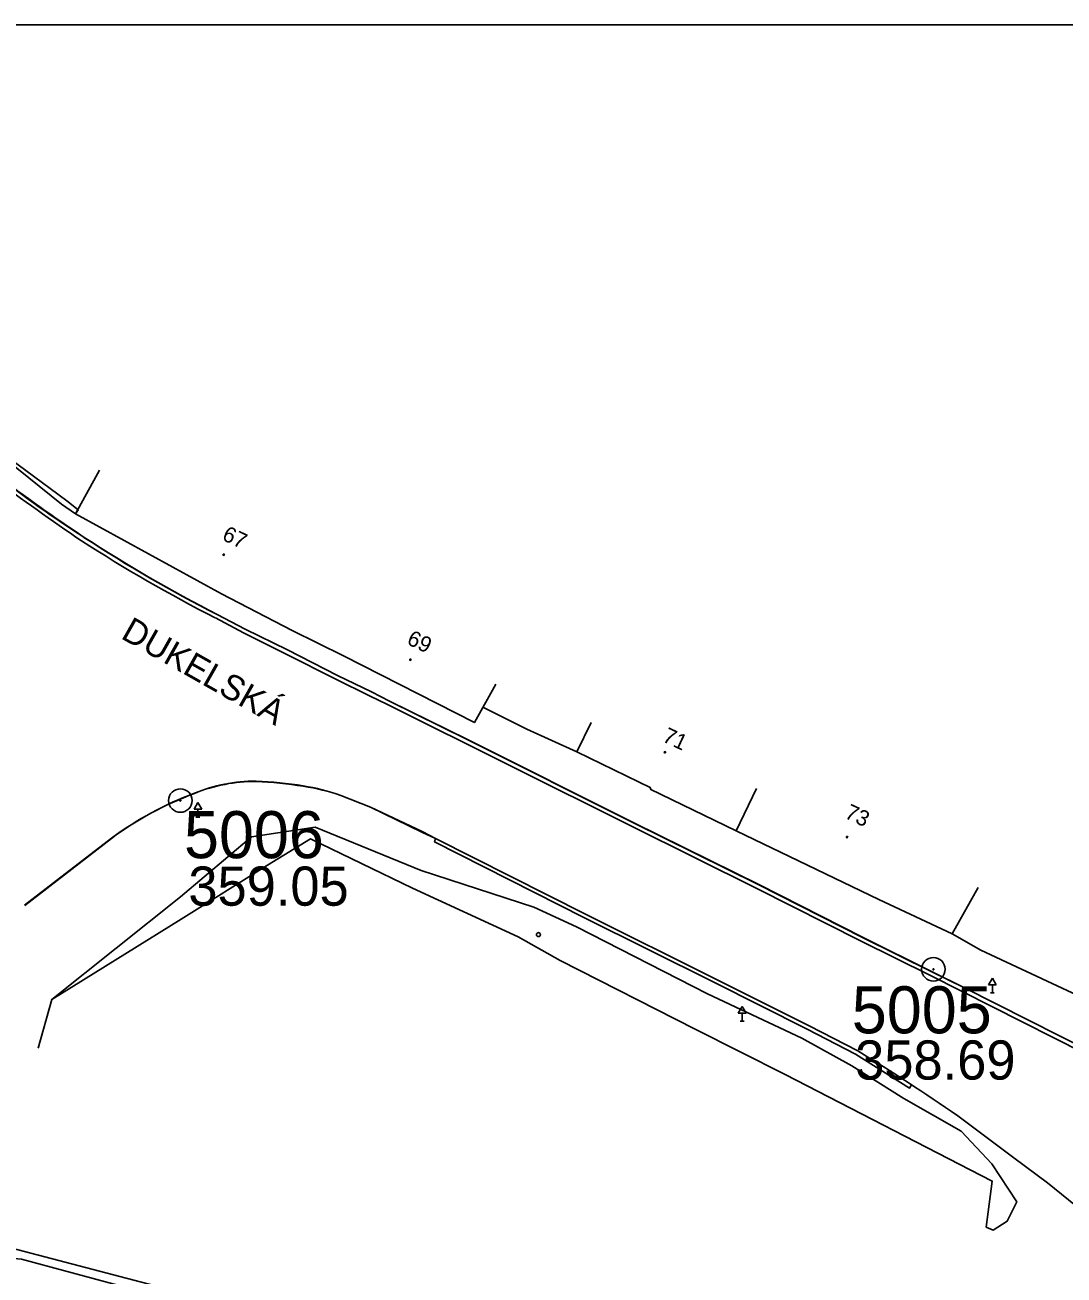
# Model space of a CAD drawing. Extents: x -590420 to -590210, y -1129531 to -1129234.
# Drawn here: x -590357.8 to -590291.5, y -1129313.6 to -1129233.9 of the extents above; entities that cross this region are included whole.
import ezdxf

# ---------------------------------------------------------------- set-up
doc = ezdxf.new("R2010")
doc.units = 0
for name, color, linetype in [('Vrstva 10', 7, 'Continuous'), ('Vrstva 12', 7, 'Continuous'), ('Vrstva 15', 7, 'Continuous'), ('Vrstva 17', 7, 'Continuous'), ('Vrstva 19', 7, 'Continuous'), ('Vrstva 23', 7, 'Continuous'), ('Vrstva 4', 7, 'Continuous'), ('Vrstva 42', 7, 'Continuous'), ('Vrstva 43', 7, 'Continuous'), ('Vrstva 5', 7, 'Continuous'), ('Vrstva 63', 7, 'Continuous'), ('Vrstva 7', 7, 'Continuous'), ('Vrstva B58', 7, 'Continuous'), ('Vrstva B59', 7, 'Continuous'), ('Vrstva B60', 7, 'Continuous')]:
    doc.layers.add(name, color=color, linetype=linetype)

msp = doc.modelspace()

# ---------------------------------------------------------------- linework, layer by layer
at = {"layer": 'Vrstva 10'}
for points in [[(-590296.46, -1129310.53), (-590296.07, -1129307.59), (-590309.27, -1129300.79), (-590315.02, -1129297.91), (-590323.62, -1129293.51), (-590326.31, -1129292.01), (-590333.05, -1129288.91), (-590339.55, -1129285.77), (-590342.29, -1129287.43), (-590347.79, -1129290.88), (-590350.6, -1129292.62), (-590356.05, -1129296), (-590356.92, -1129299.12)], [(-590366.23, -1129309.858), (-590365.68, -1129310.01), (-590339.47, -1129316.88), (-590321.05, -1129317.64), (-590313.58, -1129317.8), (-590297.47, -1129317.49), (-590297.03, -1129314.18)]]:
    msp.add_lwpolyline(points, dxfattribs=at)
at = {"layer": 'Vrstva 12'}
msp.add_line((-590325.76, -1129278.76), (-590322.56, -1129280.22), dxfattribs=at)
at = {"layer": 'Vrstva 15'}
for centre in [(-590345.086, -1129267.638), (-590333.175, -1129274.334), (-590316.948, -1129280.239), (-590305.324, -1129285.65)]:
    msp.add_circle(centre, 0.0438, dxfattribs=at)
at = {"layer": 'Vrstva 17'}
for points in [[(-590354.37, -1129264.78), (-590354.53, -1129265.04), (-590355.43, -1129264.41), (-590358.93, -1129261.58), (-590363.889, -1129257.476), (-590363.823, -1129257.404)], [(-590363.823, -1129257.404), (-590358.76, -1129261.47), (-590355.1, -1129264.21), (-590354.37, -1129264.78)]]:
    msp.add_lwpolyline(points, dxfattribs=at)
at = {"layer": 'Vrstva 19'}
for p, q in [((-590346.73, -1129283.437), (-590346.98, -1129283.87)), ((-590346.73, -1129283.437), (-590346.48, -1129283.87)), ((-590346.98, -1129283.87), (-590346.48, -1129283.87)), ((-590346.73, -1129284.37), (-590346.73, -1129283.87)), ((-590346.855, -1129284.37), (-590346.605, -1129284.37)), ((-590296.06, -1129294.647), (-590296.31, -1129295.08)), ((-590296.31, -1129295.08), (-590295.81, -1129295.08)), ((-590296.06, -1129294.647), (-590295.81, -1129295.08)), ((-590296.06, -1129295.58), (-590296.06, -1129295.08)), ((-590296.185, -1129295.58), (-590295.935, -1129295.58)), ((-590312.02, -1129296.447), (-590312.27, -1129296.88)), ((-590312.27, -1129296.88), (-590311.77, -1129296.88)), ((-590312.02, -1129296.447), (-590311.77, -1129296.88)), ((-590312.02, -1129297.38), (-590312.02, -1129296.88)), ((-590312.145, -1129297.38), (-590311.895, -1129297.38))]:
    msp.add_line(p, q, dxfattribs=at)
at = {"layer": 'Vrstva 23'}
msp.add_circle((-590325.01, -1129291.87), 0.125, dxfattribs=at)
at = {"layer": 'Vrstva 4'}
for p, q in [((-590353.004, -1129262.254), (-590354.53, -1129265.04)), ((-590321.646, -1129278.331), (-590322.56, -1129280.22)), ((-590317.847, -1129282.5), (-590322.56, -1129280.22)), ((-590317.847, -1129282.5), (-590317.89, -1129282.59)), ((-590311.103, -1129282.557), (-590312.4, -1129285.24)), ((-590296.956, -1129288.856), (-590298.63, -1129291.83))]:
    msp.add_line(p, q, dxfattribs=at)
for points in [[(-590340.71, -1129272.47), (-590345.22, -1129270.14), (-590354.53, -1129265.04)], [(-590327.733, -1129275.887), (-590329.09, -1129278.35), (-590337.45, -1129274.08)], [(-590279.69, -1129288.66), (-590283.64, -1129297), (-590284.098, -1129297.158), (-590284.104, -1129297.16), (-590284.168, -1129297.182), (-590284.174, -1129297.185), (-590285.72, -1129297.719), (-590285.725, -1129297.721), (-590285.814, -1129297.751), (-590285.82, -1129297.753), (-590286.1, -1129297.85), (-590296.8, -1129292.86), (-590298.63, -1129291.83), (-590303.3, -1129289.64), (-590312.4, -1129285.24), (-590317.89, -1129282.59)]]:
    msp.add_lwpolyline(points, dxfattribs=at)
at = {"layer": 'Vrstva 5'}
for points in [[(-590340.71, -1129272.47), (-590337.45, -1129274.08)], [(-590325.76, -1129278.76), (-590328.55, -1129277.37)]]:
    msp.add_lwpolyline(points, dxfattribs=at)
at = {"layer": 'Vrstva 63'}
msp.add_line((-590210.408, -1129233.852), (-590420.408, -1129233.852), dxfattribs=at)
at = {"layer": 'Vrstva 7'}
for p, q in [((-590345.494, -1129271.448), (-590343.72, -1129272.38)), ((-590339.04, -1129282.57), (-590339.045, -1129282.588)), ((-590357.8, -1129289.99), (-590352.24, -1129285.71)), ((-590352.24, -1129285.73), (-590357.76, -1129290.01)), ((-590288.15, -1129300.16), (-590297.88, -1129295.25))]:
    msp.add_line(p, q, dxfattribs=at)
for points in [[(-590335.65, -1129276.39), (-590337.82, -1129275.35), (-590341.02, -1129273.71), (-590343.72, -1129272.38), (-590345.51, -1129271.45)], [(-590288.27, -1129300.4), (-590298.02, -1129295.47), (-590300.04, -1129294.45), (-590304.43, -1129292.29), (-590311.08, -1129288.92), (-590319.04, -1129284.98), (-590334.63, -1129277.2), (-590335.79, -1129276.63), (-590337.94, -1129275.57), (-590341.15, -1129273.96), (-590343.82, -1129272.62), (-590345.62, -1129271.67)], [(-590297.88, -1129295.25), (-590299.92, -1129294.25), (-590304.34, -1129292.06), (-590311, -1129288.67), (-590318.91, -1129284.76), (-590329.55, -1129279.43), (-590334.52, -1129276.97), (-590335.65, -1129276.39)], [(-590335.65, -1129276.39), (-590334.51, -1129276.97), (-590329.54, -1129279.43), (-590318.92, -1129284.74), (-590310.914, -1129288.686), (-590304.35, -1129292.04), (-590299.9, -1129294.24), (-590297.88, -1129295.25)], [(-590331.58, -1129285.74), (-590332.42, -1129285.3), (-590335.73, -1129283.73), (-590337.61, -1129282.99)], [(-590331.58, -1129285.74), (-590332.45, -1129285.34), (-590335.73, -1129283.75), (-590337.61, -1129283)], [(-590356.05, -1129296), (-590347.85, -1129289.45), (-590343.32, -1129285.63), (-590339.26, -1129285.01), (-590332.5, -1129287.77), (-590325.31, -1129290.11), (-590322.58, -1129291.37), (-590314.22, -1129295.65), (-590308.21, -1129298.48), (-590305.02, -1129300.23), (-590301.7, -1129302.32), (-590298.04, -1129304.41), (-590296.09, -1129306.5), (-590294.5, -1129308.91), (-590295.11, -1129310.15), (-590296, -1129310.73), (-590296.46, -1129310.53)], [(-590331.58, -1129285.74), (-590331.64, -1129285.96), (-590322.12, -1129290.77), (-590313.82, -1129294.9), (-590307.87, -1129297.89), (-590304.79, -1129299.5), (-590301.34, -1129301.66), (-590301.21, -1129301.45)], [(-590331.58, -1129285.74), (-590322.02, -1129290.56), (-590313.73, -1129294.68), (-590307.75, -1129297.68), (-590304.65, -1129299.29)], [(-590298.27, -1129303.43), (-590294.68, -1129306.1), (-590292.55, -1129307.71), (-590288.63, -1129310.87), (-590284.63, -1129313.91), (-590282.5, -1129315.5), (-590279.13, -1129317.97), (-590276.75, -1129319.72), (-590274.87, -1129321.35)], [(-590300.68, -1129317.99), (-590311.82, -1129318.26), (-590320.49, -1129318.55), (-590330.07, -1129318.36), (-590338.22, -1129317.93), (-590347.27, -1129315.46), (-590357.99, -1129312.56), (-590368.83, -1129311.54)]]:
    msp.add_lwpolyline(points, dxfattribs=at)
for centre, radius, start, end in [((-590342.251, -1129296.224), 14.024, 70.6742, 80.80438), ((-590341.79, -1129294.849), 12.565, 70.5669, 81.85395)]:
    msp.add_arc(centre, radius, start, end, dxfattribs=at)
for centre, major_axis, ratio, start_param, end_param in [((-590290.666, -1129172.172), (113.957, 0), 0.999394, 4.060851, 4.121508), ((-590311.072, -1129200.348), (74.306, -27.239), 0.996591, 4.401942, 4.489079), ((-590300.332, -1129185.077), (-91.864, -32.809), 0.999599, 0.574857, 0.645547), ((-590305.055, -1129191.809), (12.386, -88.472), 0.999729, 5.56405, 5.673965), ((-590305.254, -1129192.035), (58.832, -67.004), 0.998165, 4.982931, 5.093006), ((-590302.449, -1129187.196), (92.07, -23.724), 0.997677, 4.388978, 4.492612), ((-590343.014, -1129292.294), (-10.164, 1.56), 0.993124, 4.864239, 5.256506), ((-590343.073, -1129292.363), (-2.43, 9.972), 0.9992, 6.03886, 6.43168), ((-590343.908, -1129307.337), (-25.384, 4.895), 0.977084, 4.747143, 4.864244), ((-590343.555, -1129302.969), (-21.447, 3.458), 0.960293, 4.701926, 4.841355), ((-590339.093, -1129303.45), (-22.039, 2.235), 0.994059, 5.17545, 5.448277), ((-590339.25, -1129303.184), (-20.892, 6.188), 0.996034, 5.360603, 5.638254), ((-590366.062, -1129400.857), (-111.738, 40.226), 0.999402, 4.450181, 4.514236)]:
    msp.add_ellipse(centre, major_axis=major_axis, ratio=ratio, start_param=start_param, end_param=end_param, dxfattribs=at)
at = {"layer": 'Vrstva B60'}
for centre, radius in [((-590347.85, -1129283.32), 0.75), ((-590347.85, -1129283.32), 0.0358), ((-590299.82, -1129294.08), 0.75), ((-590299.82, -1129294.08), 0.0358)]:
    msp.add_circle(centre, radius, dxfattribs=at)

# ---------------------------------------------------------------- texts
at = {"layer": 'Vrstva 42'}
msp.add_text('DUKELSKÁ', height=1.6, rotation=330.46573, dxfattribs=at).set_placement((-590351.713, -1129272.94))
at = {"layer": 'Vrstva 43'}
for s, p in [('67', (-590345.249, -1129266.667)), ('69', (-590333.468, -1129273.314)), ('71', (-590317.166, -1129279.521)), ('73', (-590305.543, -1129284.401))]:
    msp.add_text(s, height=1, rotation=334.88008, dxfattribs=at).set_placement(p)
at = {"layer": 'Vrstva B58'}
for s, p in [('359.05', (-590347.339, -1129290.026)), ('358.69', (-590304.809, -1129301.117))]:
    msp.add_text(s, height=2.5, dxfattribs=at).set_placement(p)
at = {"layer": 'Vrstva B59'}
for s, p in [('5006', (-590347.621, -1129286.995)), ('5005', (-590305.025, -1129298.166))]:
    msp.add_text(s, height=3, dxfattribs=at).set_placement(p)

doc.saveas('drawing.dxf')
